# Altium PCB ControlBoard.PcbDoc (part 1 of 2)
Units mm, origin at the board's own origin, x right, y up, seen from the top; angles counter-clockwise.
Board outline 111.33 x 150.7 mm, 2 copper layers (Top Layer, Bottom Layer); 147 components, 78 nets, 422 pads, 115 vias.
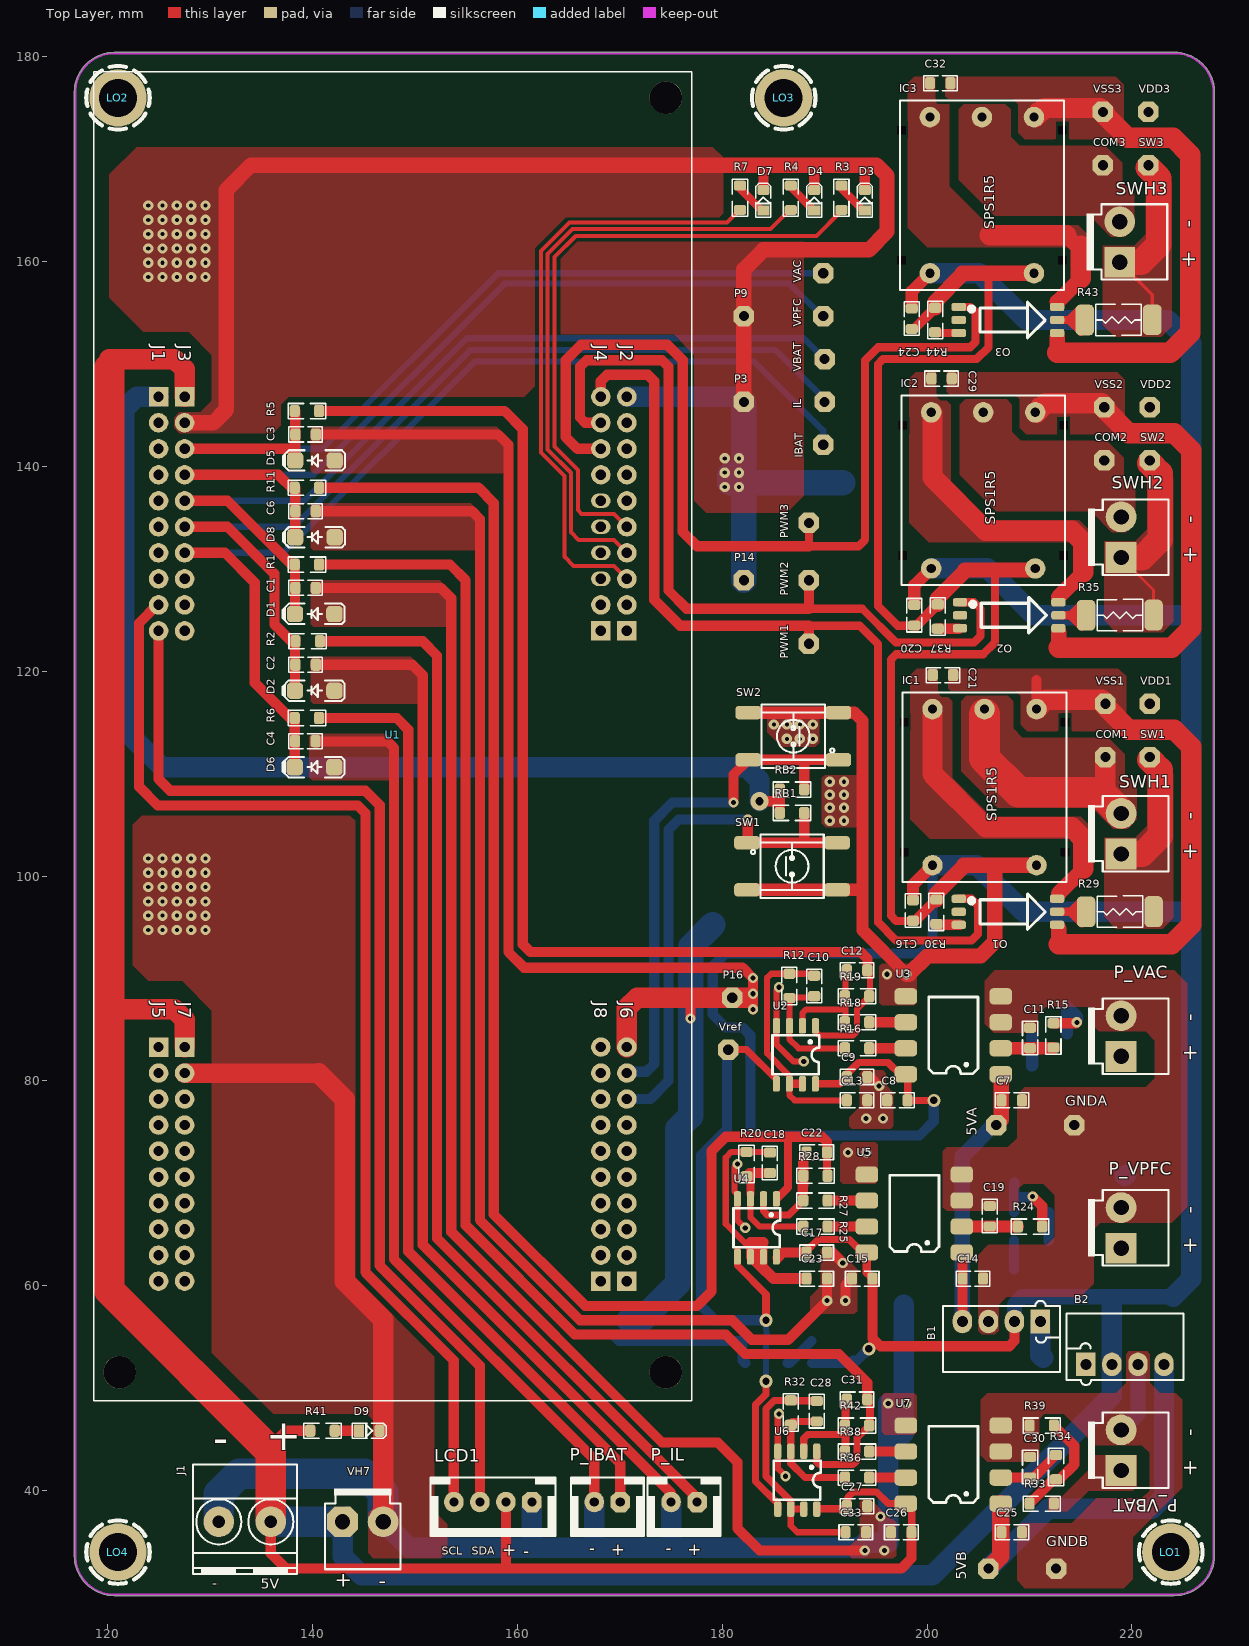
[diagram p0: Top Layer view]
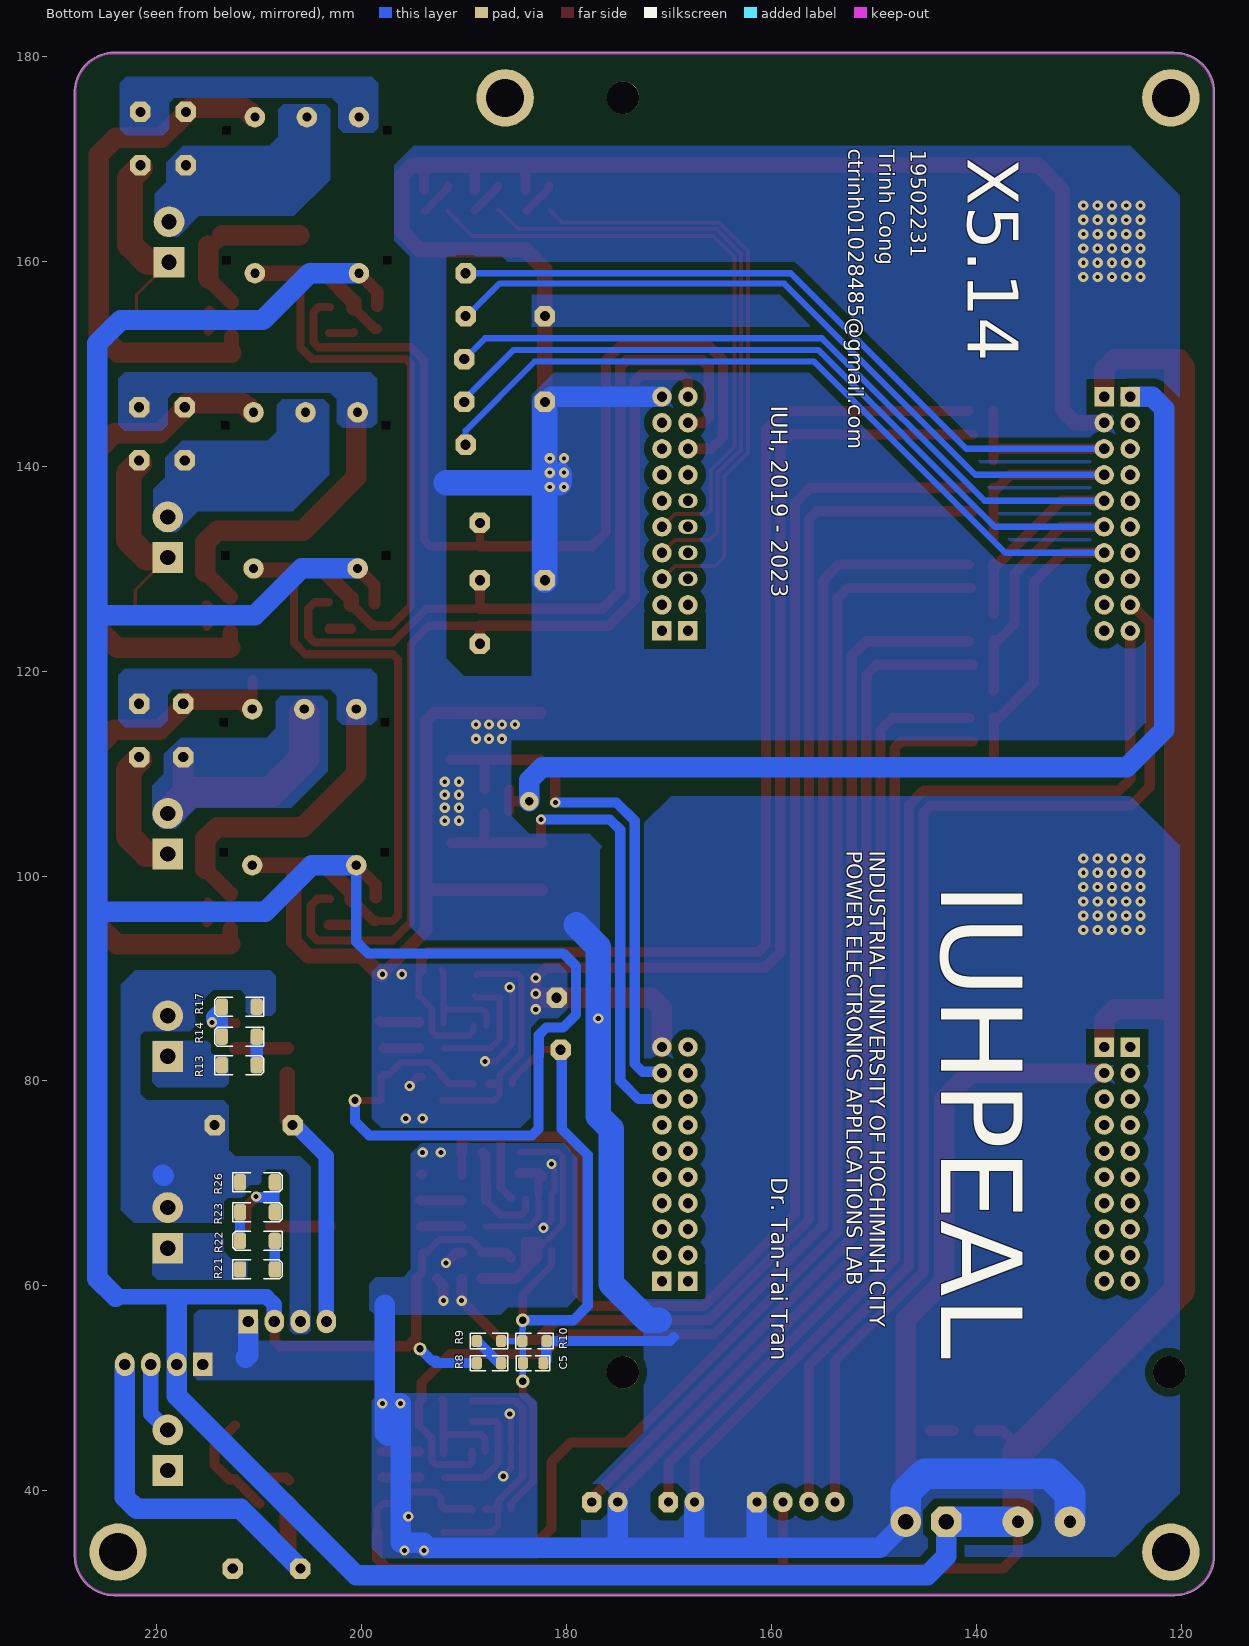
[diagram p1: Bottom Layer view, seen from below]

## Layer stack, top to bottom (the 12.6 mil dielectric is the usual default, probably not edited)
Top Solder: solder mask 0.0102, Solder Resist, Dk 3.5
Top Layer: signal copper 0.0356
Dielectric 1: dielectric 0.32, FR-4, Dk 4.8
Bottom Layer: signal copper 0.0356
Bottom Solder: solder mask 0.0102, Solder Resist, Dk 3.5

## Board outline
116.74,33.652 cw(c116.835,33.655) 116.74,33.655 116.74,176.53 cw(c116.84,176.53) 116.74,176.532 cw(c120.65,176.53) 120.649,180.44 cw(c120.649,179.463) 120.65,180.44 224.155,180.44 cw(c224.155,180.375) 224.156,180.44 cw(c224.155,176.53) 228.062,176.681 cw(c227.965,176.657) 228.065,176.657 228.065,33.655 cw(c228,33.655) 228.065,33.654 ccw(c227.088,33.654) 228.065,33.655 228.065,33.654 cw(c224.155,33.655) 224.155,29.745 120.65,29.745 cw(c120.65,29.845) 120.649,29.745 ccw(c120.649,30.722) 120.65,29.745 120.649,29.745 cw(c120.65,33.655)

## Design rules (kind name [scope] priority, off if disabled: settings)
Clearance [All] p1: gap=0.254 ignorepadtopadclearanceinfootprint=FALSE
PolygonConnect [All] p1: connectstyle=Direct reliefconductorwidth=0.254 reliefentries=4 polygonreliefangle="90 Angle" airgapwidth=0.254
RoutingVias [All] p1: holewidth=0.711 width=1.27 viastyle="Through Hole" minholewidth=0.711 minwidth=1.27 maxholewidth=0.711 maxwidth=1.27
SolderMaskExpansion [All] p1: expansion=0.102 istentingtop=FALSE
Width [All] p1: maxlimit=10 minlimit=0.3 preferedwidth=1
30 further rules are at their usual default settings.

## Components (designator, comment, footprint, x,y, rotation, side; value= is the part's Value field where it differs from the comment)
5VA "test PCB" tp_red_1p 206.756,75.692 r0 top
5VB "test PCB" tp_red_1p 205.994,32.385 r0 top
B1 "B0505S 1WR3" B0505S 207.264,56.515 r180 top
B2 "B0505S 1WR3" B0505S 219.329,52.324 r0 top
C1 "22nF" cap_0805 139.319,128.143 r180 top
C2 "4.7nF" cap_0805 139.319,120.65 r180 top
C3 "4.7nF" cap_0805 139.319,143.129 r180 top
C4 "22nF" cap_0805 139.297,113.186 r180 top
C5 "100nF" cap_0805 183.261,52.451 r0 bottom
C6 "22nF" cap_0805 139.319,135.636 r180 top
C7 "100nF" cap_0805 208.28,78.105 r180 top
C8 "100nF" cap_0805 197.104,78.105 r180 top
C9 "100nF" cap_0805 193.167,80.391 r0 top
C10 "150pF" cap_0805 188.976,89.281 r90 top
C11 "4.7nF" cap_0805 210.058,84.201 r270 top
C12 "150pF" cap_0805 193.167,90.805 r180 top
C13 "1nF" cap_0805 193.167,78.105 r180 top
C14 "100nF" cap_0805 204.47,60.706 r180 top
C15 "100nF" cap_0805 193.675,60.706 r180 top
C16 "100nF" cap_0805 198.628,96.647 r90 top
C17 "100nF" cap_0805 189.23,63.246 r0 top
C18 "150pF" cap_0805 184.658,72.009 r90 top
C19 "22nF" cap_0805 206.121,66.802 r270 top
C20 "100nF" cap_0805 198.755,125.476 r90 top
C21 "0.1uF" cap_0805 201.549,119.634 r180 top
C22 "150pF" cap_0805 189.23,73.025 r180 top
C23 "1nF" cap_0805 189.23,60.706 r180 top
C24 "100nF" cap_0805 198.501,154.432 r90 top
C25 "100nF" cap_0805 208.28,35.941 r180 top
C26 "100nF" cap_0805 197.485,35.941 r180 top
C27 "100nF" cap_0805 193.167,38.481 r0 top
C28 "150pF" cap_0805 189.23,47.752 r90 top
C29 "0.1uF" cap_0805 201.422,148.59 r180 top
C30 "22nF" cap_0805 210.058,42.291 r270 top
C31 "150pF" cap_0805 193.167,48.895 r180 top
C32 "0.1uF" cap_0805 201.295,177.419 r180 top
C33 "1nF" cap_0805 193.04,35.941 r180 top
COM1 "test PCB" tp_white_1p 217.424,111.633 r0 top
COM2 "test PCB" tp_white_1p 217.297,140.589 r0 top
COM3 "test PCB" tp_white_1p 217.17,169.418 r0 top
D1 "ZMM3V3" D_SOD80 140.208,125.603 r180 top
D2 "ZMM3V3" D_SOD80 140.208,118.11 r180 top
D3 "=VALUE" LED0805RED 193.929,165.989 r90 top
D4 "=VALUE" LED0805RED 188.976,165.989 r90 top
D5 "ZMM3V3" D_SOD80 140.23,140.589 r180 top
D6 "ZMM3V3" D_SOD80 140.186,110.646 r180 top
D7 "=VALUE" LED0805RED 184.023,165.989 r90 top
D8 "ZMM3V3" D_SOD80 140.23,133.096 r180 top
D9 "=VALUE" LED0805RED 145.542,45.847 r0 top
GNDA "test PCB" Tp_black_1p 214.376,75.692 r0 top
GNDB "test PCB" Tp_black_1p 212.598,32.385 r0 top
IBAT "test PCB" tp_yellow_1p 189.865,142.113 r180 top
IC1 "SPD1R5-5-1515" SPS1R5 213.614,99.441 r90 top
IC2 "SPD1R5-5-1515" SPS1R5 213.486,128.418 r90 top
IC3 "SPD1R5-5-1515" SPS1R5 213.359,157.247 r90 top
IL "test PCB" tp_yellow_1p 189.992,146.304 r180 top
J1 "CONN_TB2" TBG_2 133.386,36.957 r180 top
LCD1 "HHDR_4" XH_4 157.607,38.887 r180 top
LO1 "LO KHOAN" SCMH_M3P5FT 223.8,34 r0 top
LO2 "LO KHOAN" SCMH_M3P5FT 121,176 r0 top
LO3 "LO KHOAN" SCMH_M3P5FT 186,176 r0 top
LO4 "LO KHOAN" SCMH_M3P5FT 121,34 r0 top
O1 "TLP5754" TLP5754 207.899,96.52 r0 top
O2 "TLP5754" TLP5754 208.026,125.476 r0 top
O3 "TLP5754" TLP5754 207.899,154.305 r0 top
P3 "test PCB" Tp_black_1p 182.118,146.304 r90 top
P9 "test PCB" Tp_black_1p 182.118,154.686 r90 top
P14 "test PCB" Tp_black_1p 182.118,128.905 r0 top
P16 "test PCB" Tp_black_1p 180.975,88.138 r270 top
P_IBAT "HHDR_2" XH_2 168.783,38.887 r180 top
P_IL "HHDR_2" XH_2 176.276,38.887 r180 top
P_VAC "HHDR_2" VH-2#1 218.948,84.38 r90 top
P_VBAT "HHDR_2" VH-2#1 218.948,43.942 r90 top
P_VPFC "HHDR_2" VH-2#1 218.948,65.659 r90 top
PWM1 "test PCB" tp_yellow_1p 188.468,122.682 r0 top
PWM2 "test PCB" tp_yellow_1p 188.468,128.905 r0 top
PWM3 "test PCB" tp_yellow_1p 188.468,134.493 r0 top
R1 "470" R0805 139.446,130.429 r0 top
R2 "680" R0805 139.525,122.936 r0 top
R3 "1K" R0805 191.643,166.243 r90 top
R4 "1K" R0805 186.69,166.243 r90 top
R5 "680" R0805 139.446,145.415 r0 top
R6 "470" R0805 139.446,115.443 r0 top
R7 "1K" R0805 181.737,166.243 r90 top
R8 "2K" R0805 187.579,52.451 r0 bottom
R9 "2K" R0805 187.579,54.61 r0 bottom
R10 "1K" R0805 183.134,54.61 r0 bottom
R11 "470" R0805 139.446,137.922 r0 top
R12 "1.2K" R0805 186.563,89.281 r90 top
R13 "1M" R1206 211.963,81.534 r180 bottom
R14 "1M" R1206 211.963,84.328 r0 bottom
R15 "680" R0805 212.344,84.455 r90 top
R16 "1K" R0805 193.167,83.185 r180 top
R17 "1.2K" R1206 211.963,87.249 r0 bottom
R18 "1K" R0805 193.167,85.725 r180 top
R19 "1.2K" R0805 193.167,88.265 r180 top
R20 "1.5K" R0805 182.372,71.882 r90 top
R21 "1M" R1206 210.185,61.595 r180 bottom
R22 "1M" R1206 210.185,64.389 r0 bottom
R23 "1M" R1206 210.185,67.183 r180 bottom
R24 "470" R0805 210.058,65.786 r0 top
R25 "1K" R0805 189.103,65.786 r180 top
R26 "1.2K" R1206 210.185,70.104 r180 bottom
R27 "1K" R0805 189.103,68.326 r180 top
R28 "1.5K" R0805 189.103,70.739 r180 top
R29 "8R2 1W" R2512 218.821,96.52 r0 top
R30 "150R" R0805 200.914,96.52 r270 top
R32 "4.7K" R0805 186.69,47.625 r90 top
R33 "680K" R0805 211.201,38.735 r180 top
R34 "470" R0805 212.598,42.291 r270 top
R35 "8R2 1W" R2512 218.821,125.476 r0 top
R36 "3.3K" R0805 193.167,41.275 r180 top
R37 "150R" R0805 201.041,125.349 r270 top
R38 "3.3K" R0805 193.167,43.815 r180 top
R39 "3K" R0805 211.201,46.355 r0 top
R41 "1K" R0805 140.97,45.847 r0 top
R42 "4.7K" R0805 193.167,46.355 r180 top
R43 "8R2 1W" R2512 218.694,154.305 r0 top
R44 "150R" R0805 200.787,154.305 r270 top
RB1 "10K" R0805 186.817,106.172 r0 top
RB2 "10K" R0805 186.817,108.458 r0 top
SW1 "SW" SWPBS_SPDT_6X6X5 186.817,100.965 r0 top value="Button chip 4 pin"
SW1 "test PCB" Tp_blue_1p 221.742,111.633 r0 top
SW2 "SW" SWPBS_SPDT_6X6X5 186.944,113.665 r180 top value="Button chip 4 pin"
SW2 "test PCB" Tp_blue_1p 221.742,140.589 r0 top
SW3 "test PCB" Tp_blue_1p 221.615,169.418 r0 top
SWH1 "HHDR_2" VH-2#1 218.948,104.14 r90 top
SWH2 "HHDR_2" VH-2#1 218.948,133.096 r90 top
SWH3 "HHDR_2" VH-2#1 218.821,161.925 r90 top
U1 "LAUNCHXL-F28379D" MOD_LC-F28379D 147.828,113.157 r0 top
U2 "LM358" SOIC-8 187.198,82.55 r270 top
U3 "HCPL 7800" SOP-8P 202.565,86.36 r180 top
U4 "LM358" SOIC-8 183.388,65.659 r270 top
U5 "HCPL 7800" SOP-8P 198.755,68.961 r180 top
U6 "LM358" SOIC-8 187.325,41.021 r270 top
U7 "HCPL 7800" SOP-8P 202.565,44.45 r180 top
VAC "test PCB" tp_yellow_1p 189.865,158.877 r180 top
VBAT "test PCB" tp_yellow_1p 189.992,150.495 r180 top
VDD1 "test PCB" tp_red_1p 221.742,116.84 r0 top
VDD2 "test PCB" tp_red_1p 221.742,145.796 r0 top
VDD3 "test PCB" tp_red_1p 221.615,174.625 r0 top
VH7 "HHDR_2" VH-2#2 144.907,36.957 r0 top
VPFC "test PCB" tp_yellow_1p 189.865,154.686 r90 top
Vref "test PCB" tp_red_1p 180.594,83.058 r270 top
VSS1 "test PCB" Tp_black_1p 217.424,116.84 r0 top
VSS2 "test PCB" Tp_black_1p 217.297,145.796 r0 top
VSS3 "test PCB" Tp_black_1p 217.17,174.625 r0 top

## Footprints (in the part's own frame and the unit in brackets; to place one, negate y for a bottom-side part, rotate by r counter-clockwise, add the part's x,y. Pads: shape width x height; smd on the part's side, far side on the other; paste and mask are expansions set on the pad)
B0505S [mm] "B0505S 1WR3 Isolated Module DC DC Converter"
  rect 1.9x2.3 hole 1.1: 1(-3.81,0)
  oval 1.9x2.3 hole 1.1: 2(-1.27,0) 3(1.27,0) 4(3.81,0)
  silkscreen extent -5.72,-2.02 5.71,4.95, body extent -5.8,-0.92 5.8,5.08, height 10.26
cap_0805 [mm] "CHIP Capacitor, 2.0X1.3mm, 0805"
  rrect50% 1x1.2 smd mask+0.075: 1(-1,0) 2(1,0)
  silkscreen extent -1.64,-0.74 1.64,0.74, body extent -1,-0.62 1,0.63, height 1
D_SOD80 [mm] "SOD-80 500mW"
  rrect50% 1.6x1.6 smd paste-0.1: 1(-1.927,0) 2(1.927,0)
  silkscreen extent -2.93,-1 3.13,1, body extent -1.75,-0.74 1.75,0.76, height 1.5
LED0805RED [mm] "LED SMD 0805, RED"
  rect 1x1.2 smd mask+0.075: 1(-1,0)
  rrect50% 1x1.2 smd mask+0.075: 2(1,0)
  Top Layer pour cut-out: -0.5,0.8 0.5,0.8 0.5,-0.8 -0.5,-0.8
  silkscreen extent -1.65,-0.74 1.65,0.74, body extent -1,-0.63 1,0.63, height 0.7
MOD_LC-F28379D [mm]
  rect 1.9x1.9 hole 1: J1_1(-22.86,33.655) J2_1(22.86,10.795) J3_1(-20.32,33.655) J4_1(20.32,10.795) J5_1(-22.86,-29.845) J6_1(22.86,-52.705) J7_1(-20.32,-29.845) J8_1(20.32,-52.705)
  round 1.9 hole 1: J1_2(-22.86,31.115) J1_3(-22.86,28.575) J1_4(-22.86,26.035) J1_5(-22.86,23.495) J1_6(-22.86,20.955) J1_7(-22.86,18.415) J1_8(-22.86,15.875) J1_9(-22.86,13.335) J1_10(-22.86,10.795) J2_2(22.86,13.335) J2_3(22.86,15.875) J2_4(22.86,18.415) J2_5(22.86,20.955) J2_6(22.86,23.495) J2_7(22.86,26.035) J2_8(22.86,28.575) J2_9(22.86,31.115) J2_10(22.86,33.655) J3_2(-20.32,31.115) J3_3(-20.32,28.575) J3_4(-20.32,26.035) J3_5(-20.32,23.495) J3_6(-20.32,20.955) J3_7(-20.32,18.415) J3_8(-20.32,15.875) J3_9(-20.32,13.335) J3_10(-20.32,10.795) J4_2(20.32,13.335) J4_7(20.32,26.035) J4_8(20.32,28.575) J4_9(20.32,31.115) J4_10(20.32,33.655) J5_2(-22.86,-32.385) J5_3(-22.86,-34.925) J5_4(-22.86,-37.465) J5_5(-22.86,-40.005) J5_6(-22.86,-42.545) J5_7(-22.86,-45.085) J5_8(-22.86,-47.625) J5_9(-22.86,-50.165) J5_10(-22.86,-52.705) J6_2(22.86,-50.165) J6_3(22.86,-47.625) J6_4(22.86,-45.085) J6_5(22.86,-42.545) J6_6(22.86,-40.005) J6_7(22.86,-37.465) J6_8(22.86,-34.925) J6_9(22.86,-32.385) J6_10(22.86,-29.845) J7_2(-20.32,-32.385) J7_3(-20.32,-34.925) J7_4(-20.32,-37.465) J7_5(-20.32,-40.005) J7_6(-20.32,-42.545) J7_7(-20.32,-45.085) J7_8(-20.32,-47.625) J7_9(-20.32,-50.165) J7_10(-20.32,-52.705) J8_2(20.32,-50.165) J8_3(20.32,-47.625) J8_4(20.32,-45.085) J8_5(20.32,-42.545) J8_6(20.32,-40.005) J8_7(20.32,-37.465) J8_8(20.32,-34.925) J8_9(20.32,-32.385) J8_10(20.32,-29.845)
  oval 1.9x1.4 hole 1: J4_3(20.32,15.875) J4_4(20.32,18.415) J4_5(20.32,20.955) J4_6(20.32,23.495)
  round 3.175 hole 3.175 unplated: ""(-26.67,-61.595) ""(-26.67,62.865) ""(26.67,-61.595) ""(26.67,62.865)
  silkscreen extent -29.21,-64.39 29.21,65.41, body extent -24,-53.98 24,34.93, height 8.61
R0805 [mm] "0.125W 1/8W"
  rrect50% 1x1.2 smd mask+0.05: 1(-1.191,0) 2(1.191,0)
  silkscreen extent -1.83,-0.74 1.83,0.74, body extent -1.15,-0.67 1.15,0.67, height 0.76
R1206 [mm] "0.25W 1/4W"
  rrect50% 1.2x1.6 smd mask+0.05: 1(-1.699,0) 2(1.699,0)
  silkscreen extent -2.41,-0.93 2.41,0.93, body extent -1.6,-0.8 1.6,0.8, height 0.62
R2512 [mm] "CHIP RESISTOR 1WATT 2512"
  rrect50% 1.8x3 smd mask+0.05: 1(-3.287,0) 2(3.298,0.022)
  silkscreen extent -2.22,-1.52 2.22,1.55, body extent -3.15,-1.6 3.15,1.6, height 0.66
SCMH_M3P5FT [mm] "SCREW mouting, M3.5, 3.5mm diameter and 7.0mm, FlatHead"
  round 5.6 / inner round 4 / far side round 5.6 hole 3.7 mask+0.1: 1(0,0)
  Top Layer pour cut-out: 0,3.3 -0.216,3.3 -0.645,3.244 -1.063,3.132 -1.463,2.966 -1.837,2.75 -2.181,2.486 -2.486,2.181 -2.75,1.837 -2.966,1.463 -3.132,1.063 -3.244,0.645 -3.3,0.216 -3.3,0 -3.3,0 -3.3,-0.216 -3.244,-0.645 -3.132,-1.063 -2.966,-1.463 -2.75,-1.837 -2.486,-2.181 -2.181,-2.486 -1.837,-2.75 -1.463,-2.966 -1.063,-3.132 -0.645,-3.244 -0.216,-3.3 0,-3.3 0,-3.3 0.216,-3.3 0.645,-3.244 1.063,-3.132 1.463,-2.966 1.837,-2.75 2.18,-2.486 2.486,-2.181 2.75,-1.837 2.966,-1.463 3.132,-1.063 3.244,-0.645 3.3,-0.216 3.3,0 3.3,0.216 3.244,0.645 3.132,1.063 2.966,1.463 2.75,1.837 2.486,2.181 2.181,2.486 1.837,2.75 1.463,2.966 1.063,3.132 0.645,3.244 0.216,3.3 0,3.3
  Bottom Layer pour cut-out: 0,3.3 -0.216,3.3 -0.645,3.244 -1.063,3.132 -1.463,2.966 -1.837,2.75 -2.181,2.486 -2.486,2.181 -2.75,1.837 -2.966,1.463 -3.132,1.063 -3.244,0.645 -3.3,0.216 -3.3,0 -3.3,0 -3.3,-0.216 -3.244,-0.645 -3.132,-1.063 -2.966,-1.463 -2.75,-1.837 -2.486,-2.181 -2.181,-2.486 -1.837,-2.75 -1.463,-2.966 -1.063,-3.132 -0.645,-3.244 -0.216,-3.3 0,-3.3 0,-3.3 0.216,-3.3 0.645,-3.244 1.063,-3.132 1.463,-2.966 1.837,-2.75 2.18,-2.486 2.486,-2.181 2.75,-1.837 2.966,-1.463 3.132,-1.063 3.244,-0.645 3.3,-0.216 3.3,0 3.3,0.216 3.244,0.645 3.132,1.063 2.966,1.463 2.75,1.837 2.486,2.181 2.181,2.486 1.837,2.75 1.463,2.966 1.063,3.132 0.645,3.244 0.216,3.3 0,3.3
  silkscreen extent -3.1,-3.1 3.1,3.1
SOIC-8 [mm]
  rrect50% 1.5x0.7 smd: 1(-2.827,1.905) 2(-2.827,0.635) 3(-2.827,-0.635) 4(-2.827,-1.905) 5(2.827,-1.905) 6(2.827,-0.635) 7(2.827,0.635) 8(2.827,1.905)
  silkscreen extent -1.91,-2.29 1.91,2.29, body extent -3,-2.45 3,2.45, height 1.7
SOP-8P [mm]
  rrect50% 2.2x1.6 smd: 1(-4.636,5.715) 2(-4.636,3.175) 3(-4.635,0.635) 4(-4.635,-1.905) 5(4.635,-1.905) 6(4.635,0.635) 7(4.635,3.175) 8(4.635,5.715)
  silkscreen extent -2.41,-1.84 2.41,5.65, body extent -4.76,-2.99 4.89,6.81, height 3.78
SPS1R5 [mm] "SPS1R5"
  round 2 hole 0.9: 1(1.63,13.08) 2(1.63,2.92) 3(16.87,2.92) 4(16.87,8) 5(16.87,13.08)
  round 0 hole 0.8 square: ""(2.9,15.85) ""(2.9,0.15) ""(15.6,0.15) ""(15.6,15.85)
  silkscreen extent 0,0 18.5,16
SWPBS_SPDT_6X6X5 [mm] "SWITCH, PUSHBUTTON, SMD, SPDT, 6X6mm 4PIN"
  rrect50% 2.5x1.3 smd mask+0.1: 1(-4.4,2.3) 2(-4.4,-2.3) 3(4.4,2.3) 4(4.4,-2.3)
  silkscreen extent -4,-3.1 3.1,3.1, body extent -5,-3 5,3, height 5.07
TBG_2 [mm] "Terminal Block Green"
  round 3 hole 1.2: 1(-2.54,0) 2(2.54,0)
  silkscreen extent -5.08,-5.6 5.05,5.08, body extent -5,-5.5 5,5, height 14
TLP5754 [mm] "TLP5754"
  rrect50% 1.4x0.8 smd: 1(-4.8,1.27) 2(-4.8,0) 3(-4.8,-1.27) 4(4.8,-1.27) 5(4.8,0) 6(4.8,1.27)
  silkscreen extent -3.76,-1.75 3.63,1.75, body extent -5,-1.92 5,1.92, height 2.2
Tp_black_1p [mm]
  oct 2x2 hole 1: 1(0,0)
  body extent -1.15,-1.15 1.15,1.15, height 5
Tp_blue_1p [mm]
  oct 2x2 hole 1: 1(0,0)
  body extent -1.15,-1.15 1.15,1.15, height 5
tp_red_1p [mm]
  oct 2x2 hole 1: 1(0,0)
  body extent -1.15,-1.15 1.15,1.15, height 5
tp_white_1p [mm]
  oct 2x2 hole 1: 1(0,0)
  body extent -1.15,-1.15 1.15,1.15, height 5
tp_yellow_1p [mm]
  oct 2x2 hole 1: 1(0,0)
  body extent -1.15,-1.15 1.15,1.15, height 5
VH-2#1 [mm] "PW10-xx-M, JST-BxB-XH-A pitch: 2.5mm"
  rect 3x3 hole 1.5: 1(-1.98,0)
  round 3 hole 1.5: 2(1.98,0)
  silkscreen extent -3.68,-4.64 3.68,3.24, body extent -3.93,-4.8 3.93,3.7, height 10.9
VH-2#2 [mm] "PW10-xx-M, JST-BxB-XH-A pitch: 2.5mm"
  oct 3x3 hole 1.5: 1(-1.98,0)
  round 3 hole 1.5: 2(1.98,0)
  silkscreen extent -3.68,-4.64 3.68,3.24, body extent -3.93,-4.8 3.93,3.7, height 10.9
XH_2 [mm] "PW10-xx-M, JST-BxB-XH-A pitch: 2.5mm"
  oct 1.9x2 hole 0.9: 1(-1.27,0)
  oval 1.9x2 hole 0.9: 2(1.27,0)
  silkscreen extent -3.56,-2.4 3.56,3.3, body extent -3.61,-2.49 3.61,3.35, height 7.21
XH_4 [mm] "PW10-xx-M, JST-BxB-XH-A pitch: 2.5mm"
  oct 1.9x2 hole 0.9: 1(-3.81,0)
  oval 1.9x2 hole 0.9: 2(-1.27,0) 3(1.27,0) 4(3.81,0)
  silkscreen extent -6.1,-2.4 6.1,3.3, body extent -6.15,-2.49 6.15,3.35, height 7.21

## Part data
5VA 5VB COM1 COM2 COM3 GNDA GNDB IBAT IL P3 P9 P14 P16 PWM1 PWM2 PWM3 SW1 SW2 SW3 VAC VBAT VDD1 VDD2 VDD3 VPFC Vref VSS1 VSS2 VSS3: "testpin"
B1 B2: "B0505S 1WR3 Isolated Module DC DC Converter"
C1 C2 C3 C4 C5 C6 C7 C8 C9 C10 C11 C12 C13 C14 C15 C16 C17 C18 C19 C20 C21 C22 C23 C24 C25 C26 C27 C28 C29 C30 C31 C32 C33: library part "CAP SMD", "CAP SMD"
D1 D2 D5 D6 D8: library part "DIODE Zener", "DIODE ZENER"
D3 D4 D7 D9: library part LED_SMD_0805_RED, "LED, SMD, 0805, RED"
IC1 IC2 IC3: "Power supply Driver SPD1R5-5-1515 / Efficiency 80% / Input 0.381A / Output 50mA"
J1: "CONN, TERMINAL BLOCK, 5.08mm pitch"
LCD1: library part "LCD I2C", "LCD I2C JST-XH pitch: 2.5mm"
O1 O2 O3: Package="DIP-8 Toshiba"
P_IBAT P_IL: library part XH_2, "XH 2 JST-XH pitch: 2.5mm"
P_VAC P_VBAT P_VPFC SWH1 SWH2 SWH3 VH7: library part VH-2, "VH-2"
R1 R2 R3 R4 R5 R6 R7 R8 R9 R10 R11 R12 R13 R14 R15 R16 R17 R18 R19 R20 R21 R22 R23 R24 R25 R26 R27 R28 R29 R30 R32 R33 R34 R35 R36 R37 R38 R39 R41 R42 R43 R44 RB1 RB2: library part "RES SMD", "RES SMD"
SW1 SW2: library part SW4, "Switch button 4 pin"
U1: Package=None
U2 U4 U6: "LM358 Dual Opamp"
U3 U5 U7: "HCPL 7800 Isolation Amplifer, Opamp"

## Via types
v1: diameter 1, hole 0.4, Top Layer to Bottom Layer, 81 vias
v2: diameter 1, hole 0.5, Top Layer to Bottom Layer, 29 vias
v3: diameter 1.3, hole 0.711, Top Layer to Bottom Layer, 2 vias
v4: diameter 1.27, hole 0.711, Top Layer to Bottom Layer, 1 vias
v5: diameter 1.8, hole 0.8, Top Layer to Bottom Layer, 1 vias
v6: diameter 1.27, hole 0.7, Top Layer to Bottom Layer, 1 vias

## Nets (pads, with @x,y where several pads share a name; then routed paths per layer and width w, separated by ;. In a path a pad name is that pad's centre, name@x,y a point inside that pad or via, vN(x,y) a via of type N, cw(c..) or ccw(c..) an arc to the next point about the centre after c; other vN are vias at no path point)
1VA: C10.2 C13.2 R12.2 U2.6 U2.7 | length 23.6
  Top Layer w0.6: U2.6@186.563,79.723 186.563,78.613 187.071,78.105 C13.2@192.151,78.105 ; U2.6@186.563,79.883 186.563,80.518 184.389,82.692 184.389,84.5 184.389,90.075 184.785,90.472 R12.2@186.563,90.472 188.674,90.472 C10.2@188.849,90.297
  Top Layer w0.8: U2.6@186.69,79.756 186.723,79.723 U2.7@187.579,79.723
1VB: C18.2 C23.2 R20.2 U4.6 U4.7 | length 24.8
  Top Layer w0.6: 182.435,63.944 180.34,66.04 180.34,72.517 180.896,73.073 R20.2@182.372,73.073 184.594,73.073 C18.2@184.658,73.009
  Top Layer w1: 182.753,64.262 184.023,64.262
  Top Layer w1.1: 182.88,64.102 182.88,63.5 182.88,62.832 183.761,61.951 185.006,60.706 C23.2@188.23,60.706 ; U4.7@183.896,62.086 183.896,62.832 183.896,64.102
1VC: C28.2 C33.2 R32.2 U6.6 U6.7 | length 24.7
  Top Layer w0.6: U6.6@186.69,38.194 186.69,36.576 187.325,35.941 C33.2@192.024,35.941
  Top Layer w0.7: R32.2@186.563,48.768 189.214,48.768 C28.2@189.23,48.752 ; R32.2@186.69,48.816 185.073,48.806 184.277,48 184.277,41.402 186.69,38.989 U6.6@186.69,38.194 U6.7@187.96,38.194
3V3: RB1.1 RB2.1 U1.J1_1 | length 105.3
  Top Layer w1: v5(183.642,107.315) 185.626,107.315 ; RB1.1@185.626,106.378 185.626,107.315 ; RB2.1@185.626,108.458 185.626,107.315
  Bottom Layer w2: U1.J1_1@124.968,146.812 122.809,146.812 121.634,145.637 121.634,114.3 125.317,110.617 182.372,110.617 183.642,109.347 v5(183.642,107.315)
5VA: 5VA.1 B1.4 C7.2 C14.2 U3.1 U5.1 | length 32.6
  Top Layer w1: U5.1@203.391,63.246 203.47,63.167 C14.2@203.47,60.706 B1.4@203.47,56.531
  Top Layer w1.5: 5VA.1@206.756,75.692 207.264,76.2 U3.1@207.264,80.645
  Bottom Layer w1.5: B1.4@203.454,56.515 203.454,72.644 206.502,75.692 5VA.1@206.756,75.692
5VB: 5VB.1 B2.4 C25.2 U7.1 | length 39.8
  Top Layer w1.7: 5VB.1@205.994,32.385 207.201,33.591 U7.1@207.201,38.735
  Bottom Layer w2: 5VB.1@205.994,32.385 211.836,38.227 221.996,38.227 223.139,39.37 B2.4@223.139,52.324
+5: B1.2 B2.2 C8.1 C9.1 C15.1 C16.2 C17.1 C20.2 C24.2 C26.1 C27.1 IC1.1 IC2.1 IC3.1 J1.1 LCD1.2 R8.2 R41.1 U1.J3_1 U1.J7_1 U2.8 U3.8 U4.8 U5.8 U6.8 U7.8 VH7.1 | length 669.5
  Top Layer w0.7: C17.1@188.214,63.373 189.357,64.516 192.405,64.516 U5.8@193.675,63.246 ; U2.8@189.103,79.723 191.483,79.723 C9.1@192.151,80.391 ; U6.8@189.23,38.1 189.357,38.227 191.897,38.227 192.278,38.608 192.278,39.37 192.786,39.878 195.072,39.878 196.215,38.735 U7.8@197.929,38.735 198.501,38.163 C26.1@198.501,35.941 ; C9.1@192.167,80.391 192.167,80.661 193.294,81.788 196.215,81.788 197.358,80.645 U3.8@197.929,80.645 198.12,80.454 C8.1@198.12,78.105 ; C8.1@198.104,78.105 C8.1@198.12,78.105 ; v4(200.66,78.105) C8.1@198.12,78.105
  Top Layer w0.8: U5.8@193.675,63.246 U5.8@194.119,63.246 194.119,61.277 C15.1@194.691,60.706
  Top Layer w1: 135.636,44.069 137.414,45.847 R41.1@139.779,45.847 ; J1.1@135.926,36.957 135.926,33.873 137.414,32.385 197.485,32.385 198.485,33.385 C26.1@198.485,35.941 ; 136.212,42.28 136.819,42.886 ; 158.877,32.512 LCD1.2@158.877,38.887 ; U4.8@185.42,62.738 185.928,63.246 C17.1@188.23,63.246 ; v6(194.31,53.848) 194.945,54.483 ; C15.1@194.675,60.706 194.675,54.88 195.453,54.102 208.026,54.102 208.534,54.61 B1.2@208.534,56.515
  Top Layer w1.2: C24.2@198.501,155.702 198.501,157.099 IC3.1@200.279,158.877 ; C16.2@198.628,97.917 198.628,99.165 IC1.1@200.534,101.071 ; C20.2@198.755,126.619 198.755,128.397 IC2.1@200.406,130.048
  Top Layer w2: 120.142,86.995 126.492,86.995 127.508,85.979 U1.J7_1@127.508,83.312 ; 120.142,150.495 126.492,150.495 127.508,149.479 U1.J3_1@127.508,146.812
  Top Layer w3: 120.142,149.606 120.142,86.995 120.142,59.563 135.926,43.779 135.926,42.28 J1.1@135.926,37.247
  Bottom Layer w1: R8.2@188.769,52.451 192.786,52.451 ; 192.786,52.705 193.167,52.705 v6(194.31,53.848) ; IC1.1@200.534,101.071 200.534,93.6 199.39,92.456 180.34,92.456 179.07,91.186 179.07,86.487 180.34,85.217 181.991,85.217 182.729,84.479 182.729,82.423 182.753,82.399 182.753,75.311 183.388,74.676 199.263,74.676 200.66,76.073 v4(200.66,78.105)
  Bottom Layer w1.5: B1.2@208.534,56.515 208.534,58.166 209.296,58.928 224.028,58.928
  Bottom Layer w2: VH7.1@142.927,36.957 142.927,33.603 144.78,31.75 200.533,31.75 218.059,49.276 B2.2@218.059,52.324 218.059,58.42 ; IC3.1@200.279,158.877 205.105,158.877 209.677,154.305 223.52,154.305 225.806,152.019 225.806,125.476 ; IC2.1@200.406,130.048 205.867,130.048 210.439,125.476 225.806,125.476 ; IC1.1@200.534,101.071 204.872,101.071 209.423,96.52 225.806,96.52 ; 224.028,58.928 225.806,60.706 225.806,96.52 ; 225.806,96.52 225.806,125.476
  Bottom Layer w3: J1.1@135.926,36.957 VH7.1@142.875,36.957
COM1: COM1.1 IC1.4 SWH1.2 | length 23.9
  Top Layer w2: 217.398,107.67 217.424,107.696 COM1.1@217.424,111.633
  Top Layer w3: IC1.4@205.614,115.824 205.614,111.505 208.915,108.204 216.864,108.204 217.398,107.67 SWH1.2@218.948,106.12
COM2: COM2.1 IC2.4 SWH2.2
COM3: COM3.1 IC3.4 SWH3.2
GND: B1.1 B2.1 C1.1 C2.1 C3.1 C4.1 C5.1 C6.1 C8.2 C9.2 C13.1 C15.2 C16.1 C17.2 C20.1 C23.1 C24.1 C26.2 C27.2 C33.1 D1.1 D2.1 D3.2 D4.2 D5.1 D6.1 D7.2 D8.1 D9.2 IC1.2 IC2.2 IC3.2 J1.2 LCD1.1 P3.1 P9.1 P14.1 P16.1 P_IBAT.2 P_IL.2 R10.1 R30.1 R37.1 R44.1 SW1.2 SW1.4 SW2.2 SW2.4 U1.J2_10 U1.J3_2 U1.J6_10 U1.J7_2 U2.4 U3.5 U4.4 U5.5 U6.4 U7.5 VH7.2 | length 1203.5
  Top Layer w0.6: v2(181.483,71.882) 181.194,71.593 181.194,69.215 181.483,68.926 U4.4@181.483,68.486 181.483,66.421 v2(182.245,65.659) ; U6.4@185.42,43.848 185.42,42.164 v2(186.182,41.402) ; U6.4@185.42,44.45 185.42,47.371 v2(185.547,47.498) ; v2(185.547,89.154) 185.293,88.9 U2.4@185.293,85.377 185.293,83.566 186.331,82.528 186.944,81.915 v2(187.96,81.915)
  Top Layer w0.8: C9.2@194.167,80.391 194.564,80.391 195.326,79.629 v2(195.326,79.502) ; C16.1@198.501,95.631 196.977,95.631 196.469,96.139 196.469,121.158 196.977,121.666 205.486,121.666 206.629,122.809 206.629,129.286 ; C20.1@198.755,124.46 197.104,124.46 195.199,126.365 195.199,149.987 195.707,150.495 204.851,150.495 205.994,151.638 205.994,158.242 206.608,158.856 206.629,158.877 ; IC3.2@210.439,158.856 IC3.2@210.439,158.877 ; IC2.2@210.566,129.9 IC2.2@210.566,130.048
  Top Layer w1: C2.1@140.319,120.65 149.733,120.65 150.749,119.634 150.749,64.008 175.006,39.751 P_IL.2@175.006,38.887 ; C4.1@140.335,113.157 147.32,113.157 147.955,112.522 147.955,62.611 167.513,43.053 P_IBAT.2@167.513,38.887 ; C6.1@140.335,135.636 155.575,135.636 156.337,134.874 156.337,66.421 166.116,56.642 180.975,56.642 182.88,54.737 186.436,54.737 v2(190.246,58.547) 190.23,58.563 C23.1@190.23,60.706 ; C3.1@140.335,143.129 158.115,143.129 159.131,142.113 159.131,92.583 160.655,91.059 179.959,91.059 181.991,91.059 v2(183.007,90.043) v2(183.007,88.519) v2(183.007,86.995) ; C1.1@140.462,128.143 152.527,128.143 153.543,127.127 153.543,65.278 174.117,44.704 179.578,44.704 181.483,42.799 181.483,36.322 183.642,34.163 v2(193.929,34.163) ; v2(176.911,86.106) 176.911,87.376 177.038,87.503 ; D7.2@184.023,166.989 184.023,169.164 ; D4.2@188.976,166.989 188.976,169.291 189.103,169.418 ; C17.2@190.23,63.246 190.23,63.237 190.764,63.237 v2(191.77,62.23) ; v2(192.024,58.547) 192.04,58.563 192.04,60.087 C15.2@192.659,60.706 ; D3.2@193.929,166.989 193.929,169.164 ; U5.5@194.119,70.866 U5.5@194.183,70.866 ; U7.5@197.929,46.355 U7.5@197.993,46.419 ; C24.1@198.501,153.432 198.723,153.432 R44.1@200.787,155.496 ; C16.1@198.628,95.647 198.85,95.647 R30.1@200.914,97.711 ; C20.1@198.755,124.476 198.977,124.476 R37.1@201.041,126.54
  Top Layer w1.2: SW1.2@182.417,98.665 SW1.4@191.217,98.665 193.534,98.665 193.548,98.679 ; SW2.4@182.544,115.965 SW2.2@191.344,115.965 ; SW2.2@191.77,115.951 192.913,115.951 193.691,115.173 193.691,94.726 v2(197.993,90.424)
  Top Layer w1.5: U1.J3_2@127.508,144.272 130.302,144.272 131.572,145.542 131.572,167.005 133.985,169.418 184.023,169.418 189.103,169.418 193.929,169.418 195.072,169.418 196.088,168.402 196.088,162.941 194.31,161.163 184.023,161.163 182.118,159.258 P9.1@182.118,154.686 P3.1@182.118,146.177 ; v2(197.993,90.424) 198.247,90.424 200.025,92.202 205.232,92.202 206.629,93.599 206.629,101.071 ; R44.1@200.787,155.496 200.787,156.083 203.433,158.729 203.433,158.856 206.608,158.856 IC3.2@210.439,158.856 ; R30.1@200.914,97.711 200.914,98.298 203.56,100.944 203.56,101.071 206.629,101.071 ; R37.1@201.041,126.54 201.041,127.127 203.687,129.773 203.687,129.9 IC2.2@210.566,129.9 ; IC1.2@210.694,101.071 206.629,101.071
  Top Layer w1.9: U1.J7_2@127.508,80.772 140.589,80.772
  Top Layer w2: 140.589,80.772 143.129,78.232 143.129,60.452 146.887,56.694 VH7.2@146.887,36.957 ; U1.J6_10@170.688,83.312 170.688,87.122 171.704,88.138 P16.1@180.848,88.138 ; P16.1@180.975,88.138 182.372,88.138
  Bottom Layer w0.8: v2@194.056,73.152 v2@194.183,73.025 ; v2(195.707,76.327) v2@195.834,76.2
  Bottom Layer w1: 169.526,55.001 169.535,55.001 169.926,54.61 R10.1@181.943,54.61 ; R10.1@181.991,54.737 181.991,52.721 C5.1@182.261,52.451
  Bottom Layer w2: VH7.2@146.887,36.957 149.427,34.417 174.879,34.417 ; LCD1.1@161.417,38.887 161.417,34.925 161.798,34.544 ; 167.513,34.544 P_IBAT.2@167.513,38.887 ; U1.J2_10@170.688,146.812 181.483,146.812 182.118,146.177 P3.1@182.372,145.923 ; P_IL.2@175.006,38.887 175.006,34.544 174.879,34.417 ; v2@193.675,34.417 174.879,34.417 ; 193.929,34.925 196.215,34.925 v2(196.215,48.514) v2@197.739,48.514 ; 197.485,45.339 197.739,45.593 v2@197.739,48.514 ; 197.739,58.166 v2@197.739,48.514 ; B1.1@211.074,56.515 211.074,53.213 211.328,52.959
  Bottom Layer w2.5: 170.942,56.642 172.085,56.642 175.641,60.198 175.641,75.311 176.911,76.581 v2(176.911,86.106) 176.911,93.091 179.07,95.25 ; 180.721,139.192 180.721,138.43 182.118,138.43 ; P14.1@182.118,128.905 182.118,138.43 ; 182.118,139.192 P3.1@182.118,146.177 ; 191.77,138.43 182.118,138.43
  Bottom Layer w3: J1.2@130.846,36.957 130.846,39.66 132.842,41.656 145.034,41.656 146.887,39.803 VH7.2@146.887,36.957
  other v1: 123.952,94.742 125.349,94.742 126.746,94.742 128.143,94.742 129.54,94.742 123.952,96.139 125.349,96.139 126.746,96.139 128.143,96.139 129.54,96.139 123.952,97.536 125.349,97.536 126.746,97.536 128.143,97.536 129.54,97.536 123.952,98.933 125.349,98.933 126.746,98.933 128.143,98.933 129.54,98.933 123.952,100.33 125.349,100.33 126.746,100.33 128.143,100.33 129.54,100.33 123.952,101.727 125.349,101.727 126.746,101.727 128.143,101.727 129.54,101.727 190.5,105.41 191.897,105.41 190.5,106.68 191.897,106.68 190.5,107.95 191.897,107.95 190.5,109.22 191.897,109.22 186.309,113.411 187.579,113.411 188.849,113.411 185.039,114.808 186.309,114.808 187.579,114.808 188.849,114.808 180.249,138.001 181.646,138.001 180.249,139.398 181.646,139.398 180.249,140.795 181.646,140.795 123.952,158.496 125.349,158.496 126.746,158.496 128.143,158.496 129.54,158.496 123.952,159.893 125.349,159.893 126.746,159.893 128.143,159.893 129.54,159.893 123.952,161.29 125.349,161.29 126.746,161.29 128.143,161.29 129.54,161.29 123.952,162.687 125.349,162.687 126.746,162.687 128.143,162.687 129.54,162.687 123.952,164.084 125.349,164.084 126.746,164.084 128.143,164.084 129.54,164.084 123.952,165.481 125.349,165.481 126.746,165.481 128.143,165.481 129.54,165.481
  other v2: 195.834,34.163 195.453,37.465 197.993,48.514 192.278,73.025 194.056,73.025 194.056,76.327 196.088,90.424
GNDA: B1.3 C7.1 C11.1 C14.1 C19.1 GNDA.1 P_VAC.2 P_VPFC.2 R17.1 R26.1 U3.3 U3.4 U5.3 U5.4 | length 0.2
  Bottom Layer w2: 219.329,70.739 219.456,70.866
GNDB: B2.3 C25.1 C30.1 GNDB.1 P_VBAT.2 R39.1 U7.3 U7.4 | length 7.2
  Bottom Layer w1.5: P_VBAT.2@218.948,45.847 220.599,47.498 B2.3@220.599,52.324
NetC1_2: C1.2 D1.2 R1.1 U1.J3_5 VBAT.1 | length 88.3
  Top Layer w1: U1.J3_5@127.508,136.652 131.699,136.652 138.049,130.302 138.281,130.534 D1.2@138.281,125.603
  Bottom Layer w0.6: U1.J3_5@127.508,136.652 139.192,136.652 155.067,152.527 187.96,152.527 VBAT.1@189.992,150.495
NetC2_2: C2.2 D2.2 IL.1 R2.1 U1.J3_6 | length 95.1
  Top Layer w1: U1.J3_6@127.508,134.112 131.699,134.112 136.271,129.54 136.271,124.587 137.922,122.936 R2.1@138.176,122.936 ; D2.2@138.281,118.11 138.281,123.041 R2.1@138.303,123.063
  Bottom Layer w0.6: U1.J3_6@127.508,134.112 138.176,134.112 155.448,151.384 185.166,151.384 189.992,146.558 IL.1@189.992,146.304
NetC3_2: C3.2 D5.2 R5.1 U1.J3_3 VAC.1 | length 85.1
  Top Layer w1: U1.J3_3@127.508,141.732 138.303,141.732 ; D5.2@138.303,140.589 138.303,141.732 ; R5.1@138.303,145.415 138.303,141.732
  Bottom Layer w0.6: U1.J3_3@127.508,141.732 140.97,141.732 158.115,158.877 VAC.1@189.865,158.877
NetC4_2: C4.2 D6.2 IBAT.1 R6.1 U1.J3_7 | length 102.5
  Top Layer w1: U1.J3_7@127.508,131.572 131.445,131.572 134.366,128.651 134.366,118.872 138.025,115.213 R6.1@138.255,115.443 ; D6.2@138.259,110.646 R6.1@138.259,115.526
  Bottom Layer w0.6: U1.J3_7@127.508,131.572 137.16,131.572 155.829,150.241 183.134,150.241 189.865,143.51 IBAT.1@189.865,142.113
NetC6_2: C6.2 D8.2 R11.1 U1.J3_4 VPFC.1 | length 87.9
  Top Layer w1: U1.J3_4@127.508,139.192 136.652,139.192 138.089,137.755 R11.1@138.255,137.922 138.303,137.922 D8.2@138.303,133.096
  Bottom Layer w0.6: U1.J3_4@127.508,139.192 140.081,139.192 158.75,157.861 186.563,157.861 VPFC.1@189.992,154.432
NetC10_1: C10.1 R12.1 R16.2 U2.3 | length 12.4
  Top Layer w0.6: R12.1@186.436,88.138 188.833,88.138 C10.1@188.976,88.281 ; R12.1@186.563,88.09 U2.3@186.563,85.377 186.563,84.074 187.452,83.185 R16.2@191.976,83.185 R16.2@192.024,83.185
NetC11_2: C11.2 R15.1 U3.2 | length 5.1
  Top Layer w1.2: U3.2@207.201,83.185 R15.1@212.344,83.185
